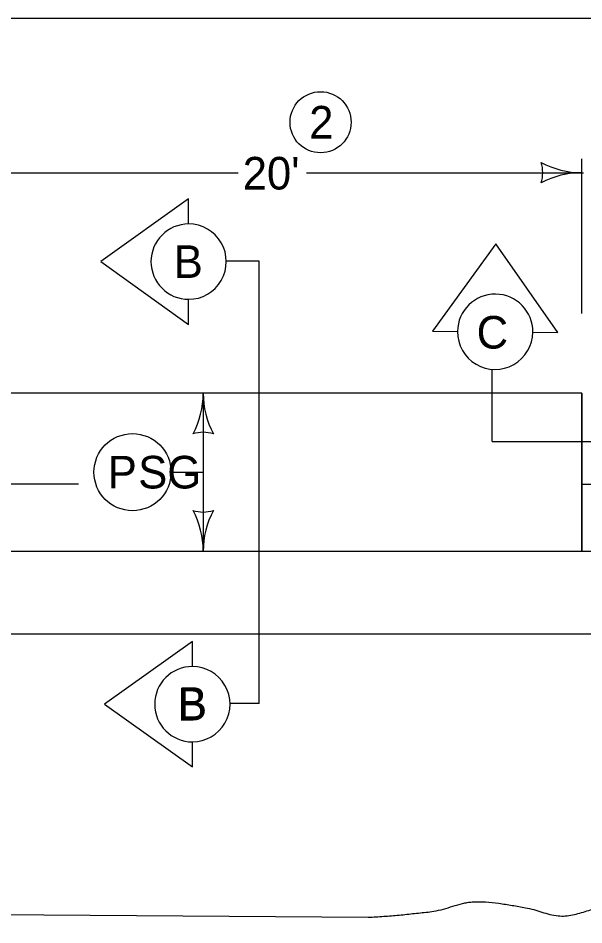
# Model space of a CAD drawing. Extents: x 10133 to 81668, y 7924 to 12229.
# Drawn here: x 11523.7 to 11801.4, y 11784 to 12229.2 of the extents above; entities that cross this region are included whole.
import ezdxf

# ---------------------------------------------------------------- set-up
doc = ezdxf.new("R2010")
doc.units = 0
for name, color, linetype in [('dsnTextFinalPlan', 7, 'Continuous'), ('Level 1', 7, 'Continuous'), ('Level 12', 7, 'Continuous'), ('Level 4', 7, 'Continuous'), ('Level 5', 7, 'Continuous'), ('Level 7', 7, 'Continuous')]:
    doc.layers.add(name, color=color, linetype=linetype)

msp = doc.modelspace()

# ---------------------------------------------------------------- linework, layer by layer
at = {"layer": 'dsnTextFinalPlan'}
for p, q in [((11800.44, 12045.08), (11495.7, 12045.08)), ((11800.44, 12045.08), (11495.7, 12045.08)), ((11800.44, 12045.08), (11800.44, 11967.5)), ((11800.44, 11967.5), (11800.44, 12045.08)), ((11800.44, 12000.48), (11978.32, 12000.48)), ((10342.6, 11967.5), (11990.07, 11967.5)), ((11495.7, 11967.5), (11800.44, 11967.5)), ((10363.81, 11926.85), (11977.6, 11926.85)), ((11366.29, 11790.23), (11695.49, 11787.77))]:
    msp.add_line(p, q, dxfattribs=at)
msp.add_circle((11579.84, 12006.29), 18.93, dxfattribs=at)
msp.add_spline([(11695.49, 11787.77), (11697.49, 11787.88), (11705.06, 11788.36), (11712.63, 11789.02), (11720.18, 11789.83), (11727.71, 11790.73), (11732.46, 11791.73), (11737.14, 11793.17), (11741.81, 11794.53), (11744.16, 11795.02), (11746.53, 11795.3), (11753.06, 11795.28), (11759.66, 11794.62), (11766.24, 11793.59), (11772.76, 11792.44), (11776.77, 11791.5), (11780.74, 11790.3), (11784.72, 11789.17), (11788.73, 11788.45), (11792.27, 11788.42), (11795.82, 11788.92), (11802.93, 11790.85), (11810.06, 11792.86), (11817.24, 11793.58), (11831.77, 11792.61), (11846.32, 11791.3), (11853.04, 11790.48), (11859.74, 11789.49), (11866.44, 11788.55), (11873.12, 11787.88), (11878.87, 11788.45), (11884.55, 11790.27), (11890.21, 11792.33), (11895.93, 11793.58), (11903.43, 11794.09), (11911.03, 11794.22), (11922.41, 11793.53), (11926.15, 11793.01), (11933.17, 11791.19), (11940.06, 11788.63), (11946.98, 11786.26), (11954.09, 11785.03), (11975.2, 11784.02)], degree=3, dxfattribs=at)
at = {"layer": 'Level 1'}
msp.add_line((10147.13, 12229.21), (13242.82, 12229.21), dxfattribs=at)
at = {"layer": 'Level 12'}
msp.add_circle((11672.15, 12178.1), 15, dxfattribs=at)
at = {"layer": 'Level 4'}
msp.add_line((11553.25, 12000.48), (10521.34, 12000.48), dxfattribs=at)
at = {"layer": 'Level 5'}
for p, q in [((11800.44, 12084.16), (11800.44, 12160.17)), ((11800.44, 12084.16), (11800.44, 12160.17)), ((11495.7, 12153.34), (11631.7, 12153.34)), ((11495.7, 12153.34), (11631.7, 12153.34)), ((11665.22, 12153.34), (11801.22, 12153.34)), ((11665.22, 12153.34), (11801.22, 12153.34)), ((11614.53, 12045.08), (11614.53, 11967.5)), ((11614.53, 12045.08), (11614.53, 11967.5)), ((11598.77, 12006.29), (11614.53, 12006.29)), ((11598.77, 12006.29), (11614.53, 12006.29))]:
    msp.add_line(p, q, dxfattribs=at)
msp.add_circle((11579.84, 12006.29), 18.93, dxfattribs=at)
msp.add_circle((11579.84, 12006.29), 18.93, dxfattribs=at)
for centre, radius, start, end in [((11764.8, 12153.34), 16.42, 342.2666, 17.7333), ((11800.44, 12195.84), 42.5, 241.9275, 270), ((11764.8, 12153.34), 16.42, 342.2666, 17.7333), ((11800.44, 12195.84), 42.5, 241.9275, 270), ((11800.44, 12110.84), 42.5, 90, 118.0725), ((11800.44, 12110.84), 42.5, 90, 118.0725), ((11572.03, 12045.08), 42.5, 331.9275, 0), ((11572.03, 12045.08), 42.5, 331.9275, 0), ((11657.03, 12045.08), 42.5, 180, 208.0725), ((11657.03, 12045.08), 42.5, 180, 208.0725), ((11614.53, 12009.45), 16.42, 72.2666, 107.7334), ((11614.53, 12009.45), 16.42, 72.2666, 107.7334), ((11614.53, 12003.14), 16.42, 252.2666, 287.7333), ((11572.03, 11967.5), 42.5, 360, 28.0725), ((11614.53, 12003.14), 16.42, 252.2666, 287.7333), ((11572.03, 11967.5), 42.5, 360, 28.0725), ((11657.03, 11967.5), 42.5, 151.9275, 180), ((11657.03, 11967.5), 42.5, 151.9275, 180)]:
    msp.add_arc(centre, radius, start, end, dxfattribs=at)
at = {"layer": 'Level 7'}
for p, q in [((11641.95, 12109.95), (11626.18, 12109.95)), ((11641.95, 12109.95), (11626.18, 12109.95)), ((11641.95, 11892.67), (11641.95, 12109.95)), ((11641.95, 11892.67), (11641.95, 12109.95)), ((11756.39, 12021.32), (11756.39, 12056.76)), ((11756.39, 12021.32), (11756.39, 12056.76)), ((11756.39, 12021.32), (11844.49, 12021.32)), ((11756.39, 12021.32), (11844.49, 12021.32)), ((11641.95, 11892.67), (11628, 11892.67)), ((11641.95, 11892.67), (11628, 11892.67))]:
    msp.add_line(p, q, dxfattribs=at)
for points in [[(11607.39, 12128.13), (11607.39, 12140.46), (11564.26, 12109.65), (11607.39, 12078.84), (11607.39, 12091.16)], [(11776.36, 12075.03), (11788.68, 12074.92), (11758.26, 12118.33), (11727.06, 12075.48), (11739.39, 12075.37)], [(11609.21, 11910.85), (11609.21, 11923.17), (11566.08, 11892.36), (11609.21, 11861.55), (11609.21, 11873.88)]]:
    msp.add_lwpolyline(points, dxfattribs=at)
for centre, start, end in [((11607.39, 12109.65), 90.0008, 269.9992), ((11607.39, 12109.65), 269.9992, 90.0008), ((11757.87, 12075.2), 359.4792, 179.4775), ((11757.87, 12075.2), 179.4775, 359.4792), ((11609.21, 11892.36), 90.0008, 269.9992), ((11609.21, 11892.36), 269.9992, 90.0008)]:
    msp.add_arc(centre, 18.49, start, end, dxfattribs=at)

# ---------------------------------------------------------------- texts
at = {"layer": 'Level 12'}
msp.add_text('2', height=16, dxfattribs=at).set_placement((11666.57, 12170.1))
at = {"layer": 'Level 5'}
for s, p in [("20'", (11633.94, 12145.07)), ("20'", (11633.94, 12145.07)), ('P', (11567.71, 11998.29)), ('P', (11567.71, 11998.29)), ('SG', (11582.63, 11998.29)), ('SG', (11582.63, 11998.29))]:
    msp.add_text(s, height=16, dxfattribs=at).set_placement(p)
at = {"layer": 'Level 7'}
for s, p in [('B', (11600.11, 12101.65)), ('B', (11600.11, 12101.65)), ('C', (11748.76, 12066.97)), ('C', (11748.76, 12066.97)), ('B', (11601.93, 11884.36)), ('B', (11601.93, 11884.36)), ('B', (11602.21, 11884.67)), ('B', (11602.21, 11884.67))]:
    msp.add_text(s, height=16, dxfattribs=at).set_placement(p)

doc.saveas('drawing.dxf')
